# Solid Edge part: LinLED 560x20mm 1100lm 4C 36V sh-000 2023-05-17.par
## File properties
Author: jaroslaw.przewlocki
Template: iso metric part.par
Last saved by: jaroslaw.przewlocki
Revision: 2
Application: Solid Edge
Gęstość: 0,000 kg/m^3
Dokładność: 0,990
Username: jaroslaw.przewlocki
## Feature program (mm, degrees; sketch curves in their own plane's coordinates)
body "unnamed Body 1"
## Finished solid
Body 1: solid body, 1422 faces, 3656 edges, 2320 vertices.
  Faces by surface: plane 816, cylinder 294, torus 128, cone 100, spline 52, sphere 32
  Edges by curve: line 2372, curve on surface 712, circle 368, ellipse 132, spline 72
Bounding box of the edges (mm; curved faces can reach further): 559.600 x 20.000 x 4.450, from (-279.8, -10, 0) to (279.8, 10, 4.45).
Cylindrical faces by radius (mm): R0.2 x92, R0.2169 x12, R0.25 x44, R0.3373 x12, R0.4 x16, R0.4006 x4, R0.4008 x4, R0.525 x4, R0.6 x40, R1 x20, R1.1 x8, R1.1989 x4, R1.199 x4, R1.2 x20, R2.15 x10
Conical faces (half-angle, radius in mm at the cone's reference point): 0.398 deg R1.1964 x4, 0.4493 deg R1.1964 x4, 0.4746 deg R1.1948 x4, 0.4758 deg R1.1948 x4, 0.5 deg R0.5056 x8, 0.5 deg R1.0082 x8, 1 deg R0.5511 x4, 10 deg R0.2132 x8, 10 deg R0.4132 x8, 16.0099 deg R1.1053 x4, 16.1249 deg R1.1279 x4, 18.8604 deg R1.0669 x8, 19.5041 deg R0.5138 x4, 19.8244 deg R0.5099 x4, 27.363 deg R0.6214 x4, 40.6434 deg R0.5161 x4, 43.3309 deg R0.4892 x4, 45 deg R0.575 x4, 45 deg R0.625 x8
Toroidal faces (ring radius, tube radius in mm): R0.0958 r0.3997 x8, R0.1076 r0.4 x4, R0.1101 r0.4001 x4, R0.1217 r0.4 x4, R0.1234 r0.4 x4, R0.1626 r0.228 x4, R0.1634 r0.2287 x4, R0.3287 r0.2001 x4, R0.3684 r0.2151 x4, R0.3703 r0.4 x4, R0.3818 r0.2 x8, R0.4166 r0.3983 x4, R0.5981 r0.197 x4, R0.5982 r0.197 x4, R0.6009 r0.3968 x4, R0.6009 r0.3969 x4, R0.6227 r0.2 x4, R0.6235 r0.2 x4, R0.8 r0.2 x8, R0.8522 r0.3 x4, R0.9002 r0.2 x4, R0.9018 r0.2 x4, R0.9197 r0.223 x4, R0.9365 r0.2 x4, R0.9663 r0.2263 x4, R0.9665 r0.2263 x4, R1.429 r1.2 x4, R1.8741 r0.2175 x4, R1.9007 r0.2 x4
Spherical faces by radius (mm): R0.2 x24, R0.6 x8
Planar faces by outward normal: +x 89, +y 95, +z 121, -x 89, -y 97, -z 17, oblique 308
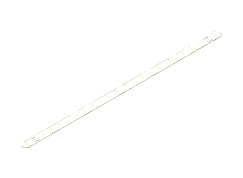
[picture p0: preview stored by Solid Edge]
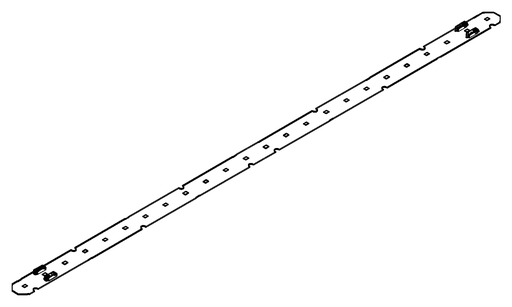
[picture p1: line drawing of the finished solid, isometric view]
